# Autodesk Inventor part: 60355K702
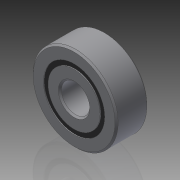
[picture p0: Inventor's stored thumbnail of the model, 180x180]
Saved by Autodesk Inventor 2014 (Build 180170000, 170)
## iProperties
Created: 2015-04
Part Number: 60355K702
Material: Generic
Document SubType Name: Modeling
Designer: Brad Factor
Density: 1 g/cm^3
Appearance: Default
Title: 60355K702.step
Description: STEP AP203
Creation Date: 2009-09-17
Sending System: SolidWorks 2007
Preprocessor: SwSTEP 2.0
Author: Brad Factor
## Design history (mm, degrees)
node "60355K7021"
node "NONE"
node "NONE_1"
node "NONE_10"
node "NONE_11"
node "Base1"
node "Base2"
node "Base11"
node "Base12"
